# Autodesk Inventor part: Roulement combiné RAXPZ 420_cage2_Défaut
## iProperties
Shininess: 64.0
Length Units: 11269
Angle Units: 11279
Time Units: 11290
Mass Units: 11283
Length Display Precision: 3
Angle Display Precision: 2
Compacted: True
Part Number: Roulement combiné RAXPZ 420_cage2_Défaut
Document SubType Name: Modeling
Created: 2006-01
Material: Par défaut
Designer: riri
Density: 0.0
Volumn: 0.0
Area: 0.0
PropertySet Name: Model Information
Control State: 0
Master: False
Checked Out: False
Author: riri
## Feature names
1. Base1
